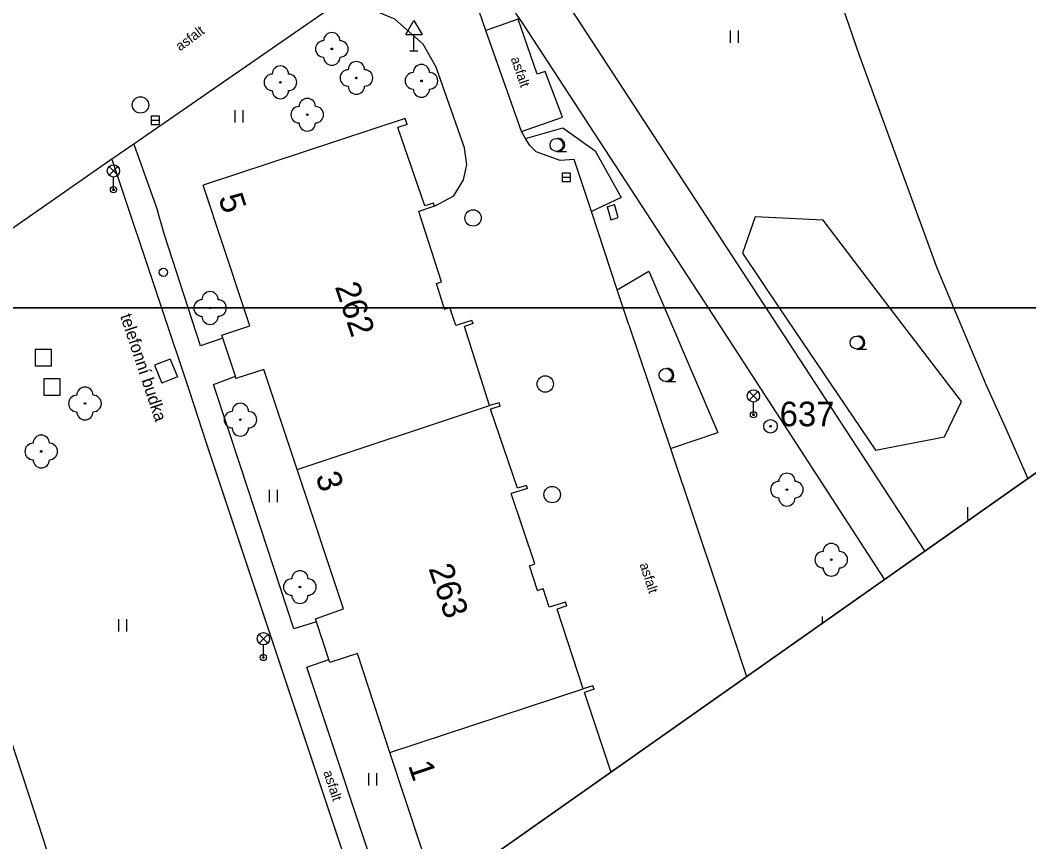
# Model space of a CAD drawing. Extents: x -492431 to -49218, y -1127123 to -112687.
# Drawn here: x -492243 to -492181.4, y -1127032.6 to -1126982.4 of the extents above; entities that cross this region are included whole.
import ezdxf

# ---------------------------------------------------------------- set-up
doc = ezdxf.new("R2010")
doc.units = 0
for name, color, linetype in [('Vrstva 1', 7, 'Continuous'), ('Vrstva 10', 7, 'Continuous'), ('Vrstva 11', 7, 'Continuous'), ('Vrstva 21', 7, 'Continuous'), ('Vrstva 22', 7, 'Continuous'), ('Vrstva 24', 7, 'Continuous'), ('Vrstva 26', 7, 'Continuous'), ('Vrstva 27', 7, 'Continuous'), ('Vrstva 31', 7, 'Continuous'), ('Vrstva 33', 7, 'Continuous'), ('Vrstva 34', 7, 'Continuous'), ('Vrstva 36', 7, 'Continuous'), ('Vrstva 40', 7, 'Continuous'), ('Vrstva 42', 7, 'Continuous'), ('Vrstva 43', 7, 'Continuous'), ('Vrstva 44', 7, 'Continuous'), ('Vrstva 5', 7, 'Continuous'), ('Vrstva 60', 7, 'Continuous'), ('Vrstva 63', 7, 'Continuous')]:
    doc.layers.add(name, color=color, linetype=linetype)

msp = doc.modelspace()

# ---------------------------------------------------------------- linework, layer by layer
at = {"layer": 'Vrstva 1'}
msp.add_lwpolyline([(-492341.24, -1127122.91), (-492133.025, -1126976.26), (-492272.695, -1126862.455), (-492313.78, -1126867.2)], dxfattribs=at)
at = {"layer": 'Vrstva 10'}
for p, q in [((-492191.78, -1126984.59), (-492194.44, -1126976.89)), ((-492187.03, -1126997.58), (-492191.78, -1126984.59)), ((-492186.02, -1127000), (-492187.03, -1126997.58)), ((-492184.03, -1127004.75), (-492186.02, -1127000)), ((-492232.7, -1127005.04), (-492231.67, -1127008.24)), ((-492182.85, -1127007.34), (-492184.03, -1127004.75)), ((-492181.502, -1127010.403), (-492182.85, -1127007.34)), ((-492231.67, -1127008.24), (-492222.27, -1127036.44)), ((-492200.42, -1127017.21), (-492198.678, -1127022.501)), ((-492242.51, -1127029.7), (-492238.59, -1127041.62))]:
    msp.add_line(p, q, dxfattribs=at)
for points in [[(-492216.02, -1126977.36), (-492212.37, -1126982.59), (-492201.01, -1127000)], [(-492187.785, -1127014.829), (-492211.62, -1126978.31)], [(-492212.42, -1126989.23), (-492214.59, -1126983.07), (-492215.99, -1126978.97)], [(-492217.72, -1126993.8), (-492216.55, -1126993.16), (-492215.95, -1126992.19), (-492215.75, -1126991.26), (-492215.89, -1126990.23), (-492217.62, -1126985.3), (-492218.41, -1126983.91), (-492220.15, -1126982.37), (-492221.26, -1126981.9), (-492222.81, -1126981.68), (-492224.34, -1126981.89), (-492236.07, -1126990)], [(-492212.42, -1126989.23), (-492209.91, -1126988.35), (-492210.97, -1126985.56), (-492211.46, -1126985.73), (-492212.62, -1126982.37), (-492214.59, -1126983.07)], [(-492206.2, -1127000), (-492206.57, -1126998.9), (-492208.14, -1126994.12), (-492209.19, -1126990.95), (-492210.06, -1126991.01), (-492211.52, -1126990.48), (-492211.91, -1126990.09), (-492212.16, -1126989.66), (-492212.42, -1126989.23)], [(-492236.07, -1126990), (-492237.41, -1126990.92)], [(-492236.07, -1126990), (-492234.63, -1126994.05)], [(-492237.41, -1126990.92), (-492247.53, -1126997.96), (-492250.02, -1126999.69)], [(-492237.41, -1126990.92), (-492234.38, -1127000)], [(-492234.2, -1126995.55), (-492234.63, -1126994.05)], [(-492232.75, -1127000), (-492234.2, -1126995.55)], [(-492234.38, -1127000), (-492232.7, -1127005.04)], [(-492230.65, -1127001.86), (-492232, -1127002.32), (-492232.75, -1127000)], [(-492205.86, -1127001.03), (-492206.2, -1127000)], [(-492201.01, -1127000), (-492190.266, -1127016.576)], [(-492205.86, -1127001.03), (-492203.32, -1127008.58), (-492200.42, -1127017.21)], [(-492224.93, -1127019.17), (-492226.3, -1127019.6), (-492229.54, -1127009.73), (-492231.22, -1127004.68), (-492229.88, -1127004.17)], [(-492251.8, -1127009.61), (-492250.62, -1127013.07), (-492249.84, -1127015.35), (-492249.33, -1127016.26), (-492248.54, -1127016.92), (-492247.57, -1127017.23), (-492246.64, -1127017.13), (-492242.51, -1127029.7)], [(-492219.23, -1127036.4), (-492220.57, -1127036.8), (-492225.52, -1127021.94), (-492224.18, -1127021.47)]]:
    msp.add_lwpolyline(points, dxfattribs=at)
at = {"layer": 'Vrstva 11'}
for p, q in [((-492233.86, -1127003.13), (-492234.81, -1127003.51)), ((-492233.86, -1127003.13), (-492233.42, -1127004.22)), ((-492234.81, -1127003.51), (-492234.37, -1127004.6)), ((-492233.42, -1127004.22), (-492234.37, -1127004.6))]:
    msp.add_line(p, q, dxfattribs=at)
at = {"layer": 'Vrstva 21'}
for p, q in [((-492198.15, -1126994.44), (-492198.93, -1126996.66)), ((-492194, -1126994.64), (-492198.15, -1126994.44)), ((-492189.92, -1127000), (-492194, -1126994.64)), ((-492198.93, -1126996.66), (-492196.68, -1127000)), ((-492196.68, -1127000), (-492190.8, -1127008.7)), ((-492185.56, -1127005.72), (-492189.92, -1127000)), ((-492186.59, -1127007.88), (-492185.56, -1127005.72)), ((-492203.32, -1127008.58), (-492200.43, -1127007.61)), ((-492190.8, -1127008.7), (-492186.59, -1127007.88))]:
    msp.add_line(p, q, dxfattribs=at)
for points in [[(-492212.16, -1126989.66), (-492209.88, -1126989), (-492207.92, -1126990.41), (-492206.33, -1126993.27), (-492208.14, -1126994.12)], [(-492206.57, -1126998.9), (-492204.64, -1126997.77), (-492203.69, -1127000)], [(-492203.69, -1127000), (-492200.43, -1127007.61)]]:
    msp.add_lwpolyline(points, dxfattribs=at)
at = {"layer": 'Vrstva 22'}
for centre in [(-492223.99, -1126984.19), (-492222.49, -1126985.96), (-492227.13, -1126986.23), (-492218.52, -1126986.14), (-492225.49, -1126988.21), (-492231.42, -1127000.01), (-492239.06, -1127005.84), (-492229.57, -1127006.83), (-492241.73, -1127008.77), (-492196.21, -1127011.1), (-492193.5, -1127015.38), (-492225.94, -1127017.05)]:
    msp.add_circle(centre, 0.05, dxfattribs=at)
for centre, start, end in [((-492223.99, -1126983.69), 360, 180), ((-492224.49, -1126984.19), 90, 270), ((-492223.49, -1126984.19), 270, 90), ((-492223.99, -1126984.69), 180, 0), ((-492227.13, -1126985.73), 360, 180), ((-492222.49, -1126985.46), 360, 180), ((-492218.52, -1126985.64), 360, 180), ((-492227.63, -1126986.23), 90, 270), ((-492226.63, -1126986.23), 270, 90), ((-492222.99, -1126985.96), 90, 270), ((-492221.99, -1126985.96), 270, 90), ((-492219.02, -1126986.14), 90, 270), ((-492218.02, -1126986.14), 270, 90), ((-492222.49, -1126986.46), 180, 0), ((-492227.13, -1126986.73), 180, 0), ((-492218.52, -1126986.64), 180, 0), ((-492225.99, -1126988.21), 90, 270), ((-492225.49, -1126987.71), 360, 180), ((-492224.99, -1126988.21), 270, 90), ((-492225.49, -1126988.71), 180, 0), ((-492231.42, -1126999.51), 360, 180), ((-492231.92, -1127000.01), 90, 270), ((-492230.92, -1127000.01), 270, 90), ((-492231.42, -1127000.51), 180, 0), ((-492239.06, -1127005.34), 360, 180), ((-492239.56, -1127005.84), 90, 270), ((-492238.56, -1127005.84), 270, 90), ((-492229.57, -1127006.33), 360, 180), ((-492239.06, -1127006.34), 180, 0), ((-492230.07, -1127006.83), 90, 270), ((-492229.07, -1127006.83), 270, 90), ((-492229.57, -1127007.33), 180, 0), ((-492241.73, -1127008.27), 360, 180), ((-492242.23, -1127008.77), 90, 270), ((-492241.23, -1127008.77), 270, 90), ((-492241.73, -1127009.27), 180, 0), ((-492196.21, -1127010.6), 360, 180), ((-492196.71, -1127011.1), 90, 270), ((-492195.71, -1127011.1), 270, 90), ((-492196.21, -1127011.6), 180, 0), ((-492194, -1127015.38), 90, 270), ((-492193.5, -1127014.88), 360, 180), ((-492193, -1127015.38), 270, 90), ((-492225.94, -1127016.55), 360, 180), ((-492193.5, -1127015.88), 180, 0), ((-492226.44, -1127017.05), 90, 270), ((-492225.44, -1127017.05), 270, 90), ((-492225.94, -1127017.55), 180, 0)]:
    msp.add_arc(centre, 0.5, start, end, dxfattribs=at)
at = {"layer": 'Vrstva 24'}
for q in [(-492206.74, -1126993.69), (-492206.95, -1126994.62)]:
    msp.add_line((-492207.19, -1126993.83), q, dxfattribs=at)
msp.add_lwpolyline([(-492206.95, -1126994.62), (-492206.5, -1126994.49), (-492206.74, -1126993.69)], dxfattribs=at)
at = {"layer": 'Vrstva 26'}
for points in [[(-492242.1, -1127003.55), (-492241.1, -1127003.55), (-492241.1, -1127002.55), (-492242.1, -1127002.55)], [(-492241.57, -1127005.33), (-492240.57, -1127005.33), (-492240.57, -1127004.33), (-492241.57, -1127004.33)]]:
    msp.add_lwpolyline(points, close=True, dxfattribs=at)
at = {"layer": 'Vrstva 27'}
for p, q in [((-492235.01, -1126988.55), (-492234.51, -1126988.55)), ((-492209.92, -1126992.03), (-492209.42, -1126992.03))]:
    msp.add_line(p, q, dxfattribs=at)
for points in [[(-492235.01, -1126988.8), (-492234.51, -1126988.8), (-492234.51, -1126988.3), (-492235.01, -1126988.3)], [(-492209.92, -1126992.28), (-492209.42, -1126992.28), (-492209.42, -1126991.78), (-492209.92, -1126991.78)]]:
    msp.add_lwpolyline(points, close=True, dxfattribs=at)
for centre in [(-492235.67, -1126987.61), (-492215.37, -1126994.51), (-492210.96, -1127004.65), (-492210.54, -1127011.4)]:
    msp.add_circle(centre, 0.5, dxfattribs=at)
at = {"layer": 'Vrstva 31'}
msp.add_circle((-492234.27, -1126997.83), 0.25, dxfattribs=at)
at = {"layer": 'Vrstva 33'}
for p, q in [((-492237.585, -1126991.375), (-492237.055, -1126991.905)), ((-492237.585, -1126991.905), (-492237.055, -1126991.375)), ((-492237.32, -1126992.79), (-492237.32, -1126992.015)), ((-492198.515, -1127005.115), (-492197.985, -1127005.645)), ((-492198.515, -1127005.645), (-492197.985, -1127005.115)), ((-492198.25, -1127006.53), (-492198.25, -1127005.755)), ((-492228.435, -1127019.935), (-492227.905, -1127020.465)), ((-492228.435, -1127020.465), (-492227.905, -1127019.935)), ((-492228.17, -1127021.35), (-492228.17, -1127020.575))]:
    msp.add_line(p, q, dxfattribs=at)
for centre, radius in [((-492237.32, -1126991.64), 0.375), ((-492237.32, -1126992.79), 0.19), ((-492237.32, -1126992.79), 0.05), ((-492198.25, -1127005.38), 0.375), ((-492198.25, -1127006.53), 0.19), ((-492198.25, -1127006.53), 0.05), ((-492228.17, -1127020.2), 0.375), ((-492228.17, -1127021.35), 0.19), ((-492228.17, -1127021.35), 0.05)]:
    msp.add_circle(centre, radius, dxfattribs=at)
at = {"layer": 'Vrstva 34'}
for p, q in [((-492219.48, -1126983.31), (-492218.98, -1126982.46)), ((-492218.98, -1126982.46), (-492218.48, -1126983.31)), ((-492219.48, -1126983.31), (-492218.48, -1126983.31)), ((-492218.98, -1126984.31), (-492218.98, -1126983.31)), ((-492219.23, -1126984.31), (-492218.73, -1126984.31))]:
    msp.add_line(p, q, dxfattribs=at)
at = {"layer": 'Vrstva 36'}
for p, q in [((-492199.66, -1126983.82), (-492199.66, -1126983.07)), ((-492199.16, -1126983.82), (-492199.16, -1126983.07)), ((-492229.9, -1126988.69), (-492229.9, -1126987.94)), ((-492229.4, -1126988.69), (-492229.4, -1126987.94)), ((-492210.27, -1126990.45), (-492210.17, -1126990.45)), ((-492210.17, -1126990.45), (-492209.67, -1126990.45)), ((-492191.95, -1127002.52), (-492191.85, -1127002.52)), ((-492191.85, -1127002.52), (-492191.35, -1127002.52)), ((-492203.61, -1127004.5), (-492203.51, -1127004.5)), ((-492203.51, -1127004.5), (-492203.01, -1127004.5)), ((-492227.8, -1127011.86), (-492227.8, -1127011.11)), ((-492227.3, -1127011.86), (-492227.3, -1127011.11)), ((-492185.16, -1127012.92), (-492185.16, -1127012.17)), ((-492237, -1127019.76), (-492237, -1127019.01)), ((-492236.5, -1127019.76), (-492236.5, -1127019.01)), ((-492194.04, -1127019.234), (-492194.04, -1127018.85)), ((-492221.74, -1127029.17), (-492221.74, -1127028.42)), ((-492221.24, -1127029.17), (-492221.24, -1127028.42))]:
    msp.add_line(p, q, dxfattribs=at)
for centre in [(-492210.27, -1126990.05), (-492191.95, -1127002.12), (-492203.61, -1127004.1)]:
    msp.add_circle(centre, 0.4, dxfattribs=at)
for centre in [(-492210.17, -1126990.05), (-492191.85, -1127002.12), (-492203.51, -1127004.1)]:
    msp.add_arc(centre, 0.4, 259.69515, 97.18076, dxfattribs=at)
at = {"layer": 'Vrstva 5'}
for p, q in [((-492219.51, -1126988.43), (-492231.84, -1126992.5)), ((-492219.39, -1126988.8), (-492219.96, -1126988.99)), ((-492218.32, -1126993.78), (-492219.96, -1126988.99)), ((-492219.39, -1126988.8), (-492219.51, -1126988.43)), ((-492229.36, -1127000), (-492231.84, -1126992.5)), ((-492217.72, -1126993.8), (-492218.68, -1126994.12)), ((-492217.78, -1126993.6), (-492218.32, -1126993.78)), ((-492217.72, -1126993.8), (-492217.78, -1126993.6)), ((-492217.29, -1126998.42), (-492218.68, -1126994.12)), ((-492217.61, -1126998.52), (-492217.29, -1126998.42)), ((-492229, -1127001.09), (-492229.36, -1127000)), ((-492217.11, -1127000.08), (-492216.78, -1126999.97)), ((-492216.41, -1127001.08), (-492216.78, -1126999.97)), ((-492230.71, -1127001.66), (-492229, -1127001.09)), ((-492215.44, -1127000.77), (-492216.41, -1127001.08)), ((-492215.36, -1127000.96), (-492215.9, -1127001.13)), ((-492215.36, -1127000.96), (-492215.44, -1127000.77)), ((-492228.14, -1127003.76), (-492229.84, -1127004.32)), ((-492226.11, -1127009.88), (-492214.36, -1127005.97)), ((-492213.78, -1127005.8), (-492214.36, -1127005.97)), ((-492213.72, -1127006.01), (-492214.3, -1127006.18)), ((-492213.72, -1127006.01), (-492213.78, -1127005.8)), ((-492212.04, -1127011.04), (-492213.04, -1127011.33)), ((-492212.1, -1127010.84), (-492212.66, -1127011.01)), ((-492212.04, -1127011.04), (-492212.1, -1127010.84)), ((-492211.93, -1127015.75), (-492211.6, -1127015.64)), ((-492211.43, -1127017.25), (-492211.93, -1127015.75)), ((-492211.43, -1127017.25), (-492211.09, -1127017.14)), ((-492210.72, -1127018.27), (-492211.09, -1127017.14)), ((-492224.99, -1127018.98), (-492223.28, -1127018.37)), ((-492209.64, -1127018.19), (-492210.24, -1127018.39)), ((-492208.65, -1127023.27), (-492210.24, -1127018.39)), ((-492209.64, -1127018.19), (-492209.72, -1127017.98)), ((-492222.42, -1127021.11), (-492224.12, -1127021.66)), ((-492220.44, -1127027.15), (-492208.65, -1127023.27)), ((-492208.05, -1127023.07), (-492208.65, -1127023.27)), ((-492207.97, -1127023.28), (-492208.57, -1127023.48)), ((-492206.95, -1127028.3), (-492208.57, -1127023.48)), ((-492207.97, -1127023.28), (-492208.05, -1127023.07)), ((-492206.876, -1127028.275), (-492206.95, -1127028.3))]:
    msp.add_line(p, q, dxfattribs=at)
for points in [[(-492217.11, -1127000.08), (-492217.61, -1126998.52)], [(-492214.36, -1127005.97), (-492215.9, -1127001.13)], [(-492229.84, -1127004.32), (-492229.88, -1127004.17), (-492230.65, -1127001.86), (-492230.71, -1127001.66)], [(-492226.11, -1127009.88), (-492228.14, -1127003.76)], [(-492212.66, -1127011.01), (-492214.3, -1127006.18)], [(-492223.28, -1127018.37), (-492226.11, -1127009.88)], [(-492211.6, -1127015.64), (-492213.04, -1127011.33)], [(-492209.72, -1127017.98), (-492210.72, -1127018.27)], [(-492224.12, -1127021.66), (-492224.18, -1127021.47), (-492224.93, -1127019.17), (-492224.99, -1127018.98)], [(-492220.44, -1127027.15), (-492222.42, -1127021.11)], [(-492217.64, -1127035.64), (-492220.44, -1127027.15)]]:
    msp.add_lwpolyline(points, dxfattribs=at)
at = {"layer": 'Vrstva 60'}
for p, q in [((-492431.031, -1127000), (-492166.731, -1127000)), ((-492166.731, -1127000), (-492431.031, -1127000))]:
    msp.add_line(p, q, dxfattribs=at)
msp.add_lwpolyline([(-492431.031, -1127000), (-492431.031, -1127013.124), (-492341.24, -1127122.91), (-492166.731, -1127000)], dxfattribs=at)
at = {"layer": 'Vrstva 63'}
for radius in [0.412, 0.05]:
    msp.add_circle((-492197.21, -1127007.23), radius, dxfattribs=at)

# ---------------------------------------------------------------- texts
at = {"layer": 'Vrstva 40'}
for rotation, p in [(36.24842, (-492233.255, -1126984.345)), (289.06902, (-492213.078, -1126984.778)), (288.05591, (-492205.209, -1127015.666)), (288.43495, (-492224.521, -1127028.346))]:
    msp.add_text('asfalt', height=0.6, rotation=rotation, dxfattribs=at).set_placement(p)
at = {"layer": 'Vrstva 42'}
msp.add_text('telefonní budka', height=0.75, rotation=288.44518, dxfattribs=at).set_placement((-492236.924, -1127000.5))
at = {"layer": 'Vrstva 43'}
for s, rotation, p in [('262', 288.45159, (-492223.814, -1126998.702)), ('263', 288.57661, (-492218.097, -1127015.905))]:
    msp.add_text(s, height=1.5, rotation=rotation, dxfattribs=at).set_placement(p)
at = {"layer": 'Vrstva 44'}
for s, rotation, p in [('5', 288.45159, (-492230.93, -1126993.281)), ('3', 288.57661, (-492225.001, -1127010.283)), ('1', 288.57138, (-492219.347, -1127027.932))]:
    msp.add_text(s, height=1.5, rotation=rotation, dxfattribs=at).set_placement(p)
at = {"layer": 'Vrstva 63'}
msp.add_text(' 637', height=1.5, dxfattribs=at).set_placement((-492197.21, -1127007.23))

doc.saveas('drawing.dxf')
